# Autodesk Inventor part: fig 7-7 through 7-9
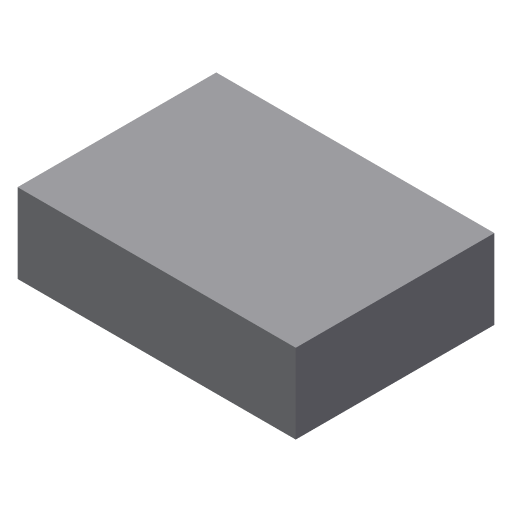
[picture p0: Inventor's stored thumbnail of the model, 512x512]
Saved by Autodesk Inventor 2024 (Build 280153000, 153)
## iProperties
Created: 2009-09
Part Number: fig 7-7 through 7-9
Document SubType Name: Modeling
Designer: Sham
Density: 1 g/cm^3
Material: Generic
Appearance: Default
Author: Sham
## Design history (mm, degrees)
sketch "Sketch1"
  geometry: L1 (-28, 20)-(0, 20); L2 (0, 20)-(0, 0); L3 (0, 0)-(-28, 0); L4 (-28, 0)-(-28, 20)
  constraints: 8 end point, 2 parallel, 1 horizontal, 1 perpendicular
extrude "Extrusion1" new body sketch "Sketch1" distance "d0" = 8; taper "d1" = 0 deg
body "Solid1"
